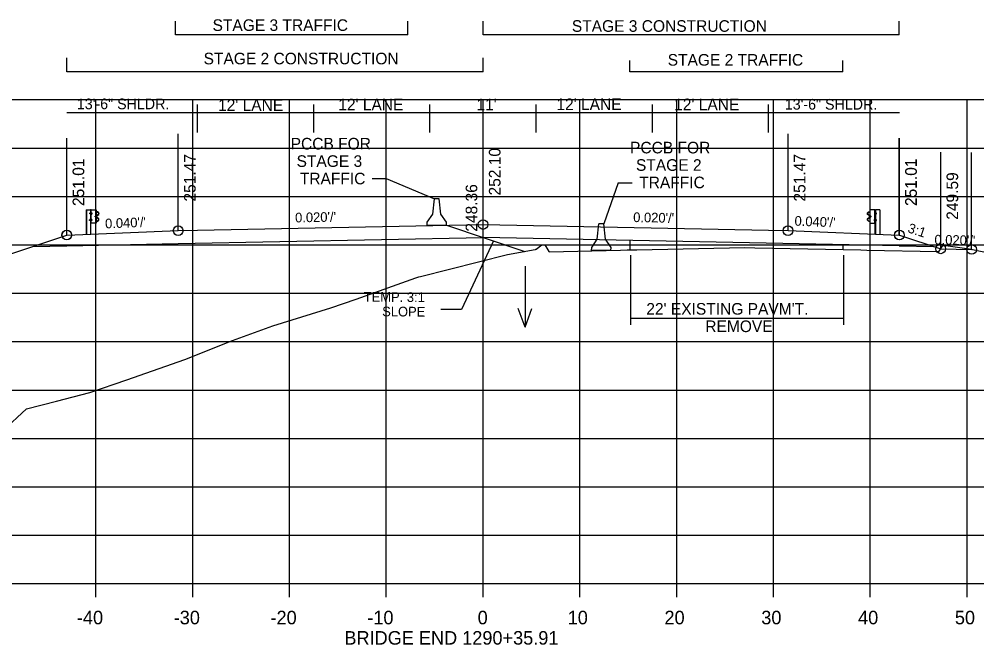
# Model space of a CAD drawing. Extents: x 1342547 to 1344156, y -1532351 to -1517216.
# Drawn here: x 1342654.9 to 1342753.9, y -1521243.9 to -1521179.3 of the extents above; entities that cross this region are included whole.
import ezdxf

# ---------------------------------------------------------------- set-up
doc = ezdxf.new("R2010")
doc.units = 0
for name, color, linetype in [('R_Alt Surface', 7, 'Continuous'), ('R_Axis', 7, 'Continuous'), ('R_Axis Annot', 7, 'Continuous'), ('R_Draft', 7, 'Continuous'), ('R_Exist Surface', 7, 'Continuous'), ('R_Fin Surface', 7, 'Continuous'), ('R_Grid', 7, 'Continuous'), ('R_MOT', 7, 'Continuous'), ('R_No Plot', 7, 'Continuous'), ('R_Water', 7, 'Continuous'), ('R_Xsect Elev', 7, 'Continuous'), ('R_Xsect Slope', 7, 'Continuous')]:
    doc.layers.add(name, color=color, linetype=linetype)

msp = doc.modelspace()

# ---------------------------------------------------------------- linework, layer by layer
at = {"layer": 'R_Alt Surface'}
for points in [[(1342659.865, -1521202.667), (1342671.365, -1521202.437), (1342702.865, -1521201.807)], [(1342745.865, -1521202.667), (1342702.865, -1521201.807)], [(1342656.338, -1521202.737), (1342659.865, -1521202.667)], [(1342745.865, -1521202.667), (1342749.391, -1521202.737)]]:
    msp.add_lwpolyline(points, dxfattribs=at)
at = {"layer": 'R_Axis'}
for p, q in [((1342562.865, -1521237.573), (1342842.865, -1521237.573)), ((1342662.865, -1521238.973), (1342662.865, -1521237.573)), ((1342672.865, -1521238.973), (1342672.865, -1521237.573)), ((1342682.865, -1521238.973), (1342682.865, -1521237.573)), ((1342692.865, -1521238.973), (1342692.865, -1521237.573)), ((1342702.865, -1521238.973), (1342702.865, -1521237.573)), ((1342712.865, -1521238.973), (1342712.865, -1521237.573)), ((1342722.865, -1521238.973), (1342722.865, -1521237.573)), ((1342732.865, -1521238.973), (1342732.865, -1521237.573)), ((1342742.865, -1521238.973), (1342742.865, -1521237.573)), ((1342752.865, -1521238.973), (1342752.865, -1521237.573))]:
    msp.add_line(p, q, dxfattribs=at)
at = {"layer": 'R_Draft'}
for p, q in [((1342671.098, -1521180.895), (1342671.098, -1521179.464)), ((1342695.098, -1521180.895), (1342695.098, -1521179.464)), ((1342702.865, -1521180.895), (1342702.865, -1521179.464)), ((1342745.865, -1521180.895), (1342745.865, -1521179.464)), ((1342695.098, -1521180.895), (1342671.098, -1521180.895)), ((1342745.865, -1521180.895), (1342702.865, -1521180.895)), ((1342659.855, -1521184.691), (1342659.855, -1521183.26)), ((1342702.865, -1521184.691), (1342702.865, -1521183.26)), ((1342718.03, -1521184.691), (1342718.03, -1521183.546)), ((1342740.032, -1521184.691), (1342740.032, -1521183.546)), ((1342702.865, -1521184.691), (1342659.855, -1521184.691)), ((1342740.032, -1521184.691), (1342718.03, -1521184.691)), ((1342661.857, -1521198.961), (1342661.857, -1521201.476)), ((1342661.887, -1521198.961), (1342661.887, -1521201.476)), ((1342662.257, -1521199.371), (1342662.257, -1521199.277)), ((1342662.312, -1521199.387), (1342662.262, -1521199.387)), ((1342662.312, -1521199.292), (1342662.263, -1521199.292)), ((1342662.312, -1521199.356), (1342662.263, -1521199.356)), ((1342662.312, -1521199.262), (1342662.264, -1521199.262)), ((1342662.312, -1521199.356), (1342662.269, -1521199.356)), ((1342662.312, -1521199.387), (1342662.312, -1521199.262)), ((1342662.382, -1521198.959), (1342662.313, -1521198.962)), ((1342662.348, -1521201.477), (1342662.348, -1521198.959)), ((1342662.382, -1521198.959), (1342662.376, -1521198.959)), ((1342662.437, -1521199.33), (1342662.381, -1521199.33)), ((1342662.388, -1521199.392), (1342662.438, -1521199.392)), ((1342662.389, -1521199.267), (1342662.438, -1521199.267)), ((1342662.438, -1521199.267), (1342662.438, -1521199.392)), ((1342662.881, -1521200.327), (1342662.881, -1521198.967)), ((1342663.025, -1521199.175), (1342662.913, -1521199.115)), ((1342663.012, -1521199.191), (1342662.919, -1521199.141)), ((1342662.967, -1521199.507), (1342663.139, -1521199.402)), ((1342662.98, -1521199.528), (1342663.152, -1521199.423)), ((1342663.142, -1521199.295), (1342663.012, -1521199.191)), ((1342663.155, -1521199.279), (1342663.025, -1521199.175)), ((1342742.567, -1521199.281), (1342742.697, -1521199.177)), ((1342742.742, -1521199.53), (1342742.57, -1521199.425)), ((1342742.58, -1521199.297), (1342742.71, -1521199.193)), ((1342742.755, -1521199.509), (1342742.583, -1521199.404)), ((1342742.697, -1521199.177), (1342742.809, -1521199.117)), ((1342742.71, -1521199.193), (1342742.803, -1521199.143)), ((1342742.841, -1521200.329), (1342742.841, -1521198.969)), ((1342743.333, -1521199.269), (1342743.284, -1521199.269)), ((1342743.284, -1521199.269), (1342743.284, -1521199.394)), ((1342743.334, -1521199.394), (1342743.284, -1521199.394)), ((1342743.285, -1521199.332), (1342743.341, -1521199.332)), ((1342743.34, -1521198.961), (1342743.346, -1521198.961)), ((1342743.34, -1521198.961), (1342743.409, -1521198.964)), ((1342743.374, -1521201.479), (1342743.374, -1521198.961)), ((1342743.41, -1521199.389), (1342743.41, -1521199.264)), ((1342743.41, -1521199.264), (1342743.458, -1521199.264)), ((1342743.41, -1521199.294), (1342743.459, -1521199.294)), ((1342743.41, -1521199.358), (1342743.453, -1521199.358)), ((1342743.41, -1521199.358), (1342743.459, -1521199.358)), ((1342743.41, -1521199.389), (1342743.46, -1521199.389)), ((1342743.465, -1521199.373), (1342743.465, -1521199.279)), ((1342743.835, -1521198.963), (1342743.835, -1521201.478)), ((1342743.865, -1521198.963), (1342743.865, -1521201.478)), ((1342662.247, -1521200.061), (1342662.247, -1521199.966)), ((1342662.302, -1521199.982), (1342662.252, -1521199.982)), ((1342662.302, -1521200.046), (1342662.252, -1521200.046)), ((1342662.302, -1521200.076), (1342662.252, -1521200.076)), ((1342662.302, -1521199.951), (1342662.253, -1521199.951)), ((1342662.302, -1521200.046), (1342662.259, -1521200.046)), ((1342662.302, -1521200.076), (1342662.302, -1521199.951)), ((1342662.381, -1521200.327), (1342662.347, -1521200.327)), ((1342662.437, -1521200.014), (1342662.381, -1521200.014)), ((1342662.438, -1521200.076), (1342662.388, -1521200.076)), ((1342662.438, -1521199.951), (1342662.389, -1521199.951)), ((1342662.438, -1521200.076), (1342662.438, -1521199.951)), ((1342662.813, -1521199.693), (1342662.813, -1521199.598)), ((1342662.868, -1521199.708), (1342662.818, -1521199.708)), ((1342662.868, -1521199.614), (1342662.819, -1521199.614)), ((1342662.868, -1521199.678), (1342662.819, -1521199.678)), ((1342662.868, -1521199.583), (1342662.82, -1521199.583)), ((1342662.868, -1521199.678), (1342662.825, -1521199.678)), ((1342662.868, -1521199.708), (1342662.868, -1521199.583)), ((1342662.909, -1521200.165), (1342663.017, -1521200.11)), ((1342662.917, -1521200.184), (1342663.031, -1521200.126)), ((1342662.92, -1521199.707), (1342662.922, -1521199.576)), ((1342662.944, -1521199.708), (1342662.946, -1521199.576)), ((1342663.117, -1521199.879), (1342662.962, -1521199.782)), ((1342663.129, -1521199.859), (1342662.975, -1521199.762)), ((1342663.017, -1521200.11), (1342663.143, -1521200.001)), ((1342663.031, -1521200.126), (1342663.157, -1521200.017)), ((1342742.691, -1521200.128), (1342742.565, -1521200.019)), ((1342742.705, -1521200.112), (1342742.579, -1521200.003)), ((1342742.593, -1521199.861), (1342742.747, -1521199.764)), ((1342742.605, -1521199.881), (1342742.76, -1521199.784)), ((1342742.805, -1521200.186), (1342742.691, -1521200.128)), ((1342742.813, -1521200.167), (1342742.705, -1521200.112)), ((1342742.778, -1521199.71), (1342742.776, -1521199.578)), ((1342742.802, -1521199.709), (1342742.8, -1521199.578)), ((1342742.854, -1521199.71), (1342742.854, -1521199.585)), ((1342742.854, -1521199.585), (1342742.902, -1521199.585)), ((1342742.854, -1521199.616), (1342742.903, -1521199.616)), ((1342742.854, -1521199.68), (1342742.897, -1521199.68)), ((1342742.854, -1521199.68), (1342742.903, -1521199.68)), ((1342742.854, -1521199.71), (1342742.904, -1521199.71)), ((1342742.909, -1521199.695), (1342742.909, -1521199.6)), ((1342743.284, -1521200.078), (1342743.284, -1521199.953)), ((1342743.284, -1521199.953), (1342743.333, -1521199.953)), ((1342743.284, -1521200.078), (1342743.334, -1521200.078)), ((1342743.285, -1521200.016), (1342743.341, -1521200.016)), ((1342743.341, -1521200.329), (1342743.375, -1521200.329)), ((1342743.42, -1521200.078), (1342743.42, -1521199.953)), ((1342743.42, -1521199.953), (1342743.469, -1521199.953)), ((1342743.42, -1521199.984), (1342743.47, -1521199.984)), ((1342743.42, -1521200.048), (1342743.463, -1521200.048)), ((1342743.42, -1521200.048), (1342743.47, -1521200.048)), ((1342743.42, -1521200.078), (1342743.47, -1521200.078)), ((1342743.475, -1521200.063), (1342743.475, -1521199.968)), ((1342699.091, -1521200.549), (1342707.186, -1521203.247)), ((1342718.029, -1521202.11), (1342718.029, -1521203.094)), ((1342740.03, -1521202.55), (1342740.03, -1521203.059)), ((1342718.085, -1521203.626), (1342718.085, -1521210.823)), ((1342740.087, -1521203.626), (1342740.087, -1521210.823)), ((1342718.085, -1521210.15), (1342740.087, -1521210.15))]:
    msp.add_line(p, q, dxfattribs=at)
for points in [[(1342691.397, -1521195.735), (1342692.838, -1521195.735)], [(1342692.838, -1521195.735), (1342697.84, -1521197.818)], [(1342716.811, -1521196.157), (1342715.327, -1521200.415)], [(1342716.811, -1521196.157), (1342718.253, -1521196.157)], [(1342661.857, -1521198.961), (1342662.313, -1521198.962), (1342662.312, -1521201.477)], [(1342743.865, -1521198.963), (1342743.409, -1521198.964), (1342743.411, -1521201.479)]]:
    msp.add_lwpolyline(points, dxfattribs=at)
for points in [[(1342662.255, -1521199.293), (1342662.255, -1521199.355), (1342662.23, -1521199.355), (1342662.23, -1521199.293)], [(1342662.311, -1521199.242), (1342662.311, -1521199.41), (1342662.321, -1521199.41), (1342662.321, -1521199.242)], [(1342662.907, -1521198.96), (1342662.906, -1521200.327), (1342662.381, -1521200.327), (1342662.382, -1521198.959)], [(1342662.437, -1521199.267), (1342662.437, -1521199.392), (1342662.382, -1521199.392), (1342662.382, -1521199.267)], [(1342742.815, -1521198.962), (1342742.816, -1521200.329), (1342743.341, -1521200.329), (1342743.34, -1521198.961)], [(1342743.285, -1521199.269), (1342743.285, -1521199.394), (1342743.34, -1521199.394), (1342743.34, -1521199.269)], [(1342743.411, -1521199.244), (1342743.411, -1521199.412), (1342743.401, -1521199.412), (1342743.401, -1521199.244)], [(1342743.467, -1521199.295), (1342743.467, -1521199.357), (1342743.492, -1521199.357), (1342743.492, -1521199.295)], [(1342662.244, -1521199.982), (1342662.244, -1521200.045), (1342662.219, -1521200.045), (1342662.219, -1521199.982)], [(1342662.3, -1521199.931), (1342662.3, -1521200.099), (1342662.31, -1521200.099), (1342662.31, -1521199.931)], [(1342662.437, -1521199.951), (1342662.437, -1521200.076), (1342662.382, -1521200.076), (1342662.382, -1521199.951)], [(1342662.811, -1521199.614), (1342662.811, -1521199.677), (1342662.786, -1521199.677), (1342662.786, -1521199.614)], [(1342662.867, -1521199.563), (1342662.867, -1521199.731), (1342662.877, -1521199.731), (1342662.877, -1521199.563)], [(1342742.855, -1521199.565), (1342742.855, -1521199.733), (1342742.845, -1521199.733), (1342742.845, -1521199.565)], [(1342742.911, -1521199.616), (1342742.911, -1521199.679), (1342742.936, -1521199.679), (1342742.936, -1521199.616)], [(1342743.285, -1521199.953), (1342743.285, -1521200.078), (1342743.34, -1521200.078), (1342743.34, -1521199.953)], [(1342743.422, -1521199.933), (1342743.422, -1521200.101), (1342743.412, -1521200.101), (1342743.412, -1521199.933)], [(1342743.478, -1521199.984), (1342743.478, -1521200.047), (1342743.503, -1521200.047), (1342743.503, -1521199.984)]]:
    msp.add_lwpolyline(points, close=True, dxfattribs=at)
for centre, radius, start, end in [((1342662.28, -1521199.278), 0.022, 134.57445, 222.22441), ((1342662.35, -1521199.325), 0.0922, 159.74227, 200.25773), ((1342662.283, -1521199.372), 0.025, 140.93341, 216.62337), ((1342663.008, -1521199.583), 0.0865, 118.10599, 175.04439), ((1342663.109, -1521199.348), 0.062, 299.24991, 57.97825), ((1342663.109, -1521199.348), 0.0856, 299.24991, 57.97825), ((1342742.613, -1521199.35), 0.0856, 122.02175, 240.75009), ((1342742.613, -1521199.35), 0.062, 122.02175, 240.75009), ((1342742.714, -1521199.586), 0.0865, 4.95561, 61.89401), ((1342743.443, -1521199.28), 0.022, 317.77559, 45.42555), ((1342743.373, -1521199.327), 0.0922, 339.74227, 20.25773), ((1342743.44, -1521199.374), 0.025, 323.37663, 39.06659), ((1342662.269, -1521199.967), 0.022, 134.57445, 222.22441), ((1342662.339, -1521200.014), 0.0922, 159.74227, 200.25773), ((1342662.272, -1521200.061), 0.025, 140.93341, 216.62337), ((1342662.836, -1521199.599), 0.022, 134.57445, 222.22441), ((1342662.906, -1521199.646), 0.0922, 159.74227, 200.25773), ((1342662.839, -1521199.693), 0.025, 140.93341, 216.62337), ((1342662.99, -1521199.717), 0.0703, 171.78044, 246.85364), ((1342662.939, -1521199.65), 0.0453, 282.95537, 86.06973), ((1342662.99, -1521199.717), 0.0462, 171.78044, 246.85364), ((1342663.008, -1521199.583), 0.0622, 118.10599, 175.04439), ((1342663.073, -1521199.952), 0.0854, 325.21842, 59.11995), ((1342663.073, -1521199.952), 0.109, 325.21843, 59.11995), ((1342742.649, -1521199.954), 0.109, 120.88005, 214.78158), ((1342742.649, -1521199.954), 0.0854, 120.88005, 214.78158), ((1342742.783, -1521199.652), 0.0453, 93.93027, 257.04463), ((1342742.714, -1521199.586), 0.0622, 4.95561, 61.89401), ((1342742.732, -1521199.72), 0.0462, 293.14636, 8.21956), ((1342742.732, -1521199.72), 0.0703, 293.14636, 8.21956), ((1342742.887, -1521199.601), 0.022, 317.77559, 45.42555), ((1342742.816, -1521199.648), 0.0922, 339.74227, 20.25773), ((1342742.884, -1521199.696), 0.025, 323.37663, 39.06659), ((1342743.453, -1521199.969), 0.022, 317.77559, 45.42555), ((1342743.383, -1521200.016), 0.0922, 339.74227, 20.25773), ((1342743.45, -1521200.064), 0.025, 323.37663, 39.06659)]:
    msp.add_arc(centre, radius, start, end, dxfattribs=at)
at = {"layer": 'R_Exist Surface'}
msp.add_lwpolyline([(1342653.241, -1521221.788), (1342655.707, -1521219.521), (1342658.812, -1521218.723), (1342662.225, -1521217.827), (1342666.057, -1521216.519), (1342672.056, -1521214.425), (1342676.962, -1521212.459), (1342681.13, -1521210.936), (1342687.121, -1521209.066), (1342689.749, -1521208.198), (1342695.909, -1521205.996), (1342696.23, -1521205.883), (1342696.414, -1521205.831), (1342705.387, -1521203.583), (1342708.254, -1521203.048), (1342708.272, -1521203.04), (1342708.322, -1521203.031), (1342708.331, -1521203.022), (1342708.941, -1521202.588), (1342709.103, -1521202.588), (1342709.241, -1521202.588), (1342709.653, -1521203.248), (1342709.68, -1521203.285), (1342717.047, -1521203.122), (1342717.747, -1521203.104), (1342718.747, -1521203.082), (1342729.921, -1521202.855), (1342730.933, -1521202.877), (1342741.887, -1521203.1), (1342742.507, -1521203.111), (1342749.857, -1521203.262), (1342749.942, -1521203.263), (1342749.986, -1521203.225), (1342750.36, -1521202.645), (1342750.487, -1521202.645), (1342750.66, -1521202.645), (1342753.093, -1521203.003), (1342754.766, -1521203.338)], dxfattribs=at)
at = {"layer": 'R_Fin Surface'}
msp.add_lwpolyline([(1342555.604, -1521213.2), (1342586.278, -1521223.424), (1342594.278, -1521223.424), (1342659.855, -1521201.565), (1342659.865, -1521201.563), (1342671.365, -1521201.103), (1342673.365, -1521201.063), (1342702.865, -1521200.473), (1342732.365, -1521201.063), (1342734.365, -1521201.103), (1342745.865, -1521201.564), (1342745.875, -1521201.565), (1342750.14, -1521202.987), (1342753.332, -1521203.051)], dxfattribs=at)
at = {"layer": 'R_Grid'}
for p, q in [((1342562.865, -1521187.573), (1342842.865, -1521187.573)), ((1342662.865, -1521237.573), (1342662.865, -1521187.573)), ((1342672.865, -1521237.573), (1342672.865, -1521187.573)), ((1342682.865, -1521237.573), (1342682.865, -1521187.573)), ((1342692.865, -1521237.573), (1342692.865, -1521187.573)), ((1342702.865, -1521237.573), (1342702.865, -1521187.573)), ((1342712.865, -1521237.573), (1342712.865, -1521187.573)), ((1342722.865, -1521237.573), (1342722.865, -1521187.573)), ((1342732.865, -1521237.573), (1342732.865, -1521187.573)), ((1342742.865, -1521237.573), (1342742.865, -1521187.573)), ((1342752.865, -1521237.573), (1342752.865, -1521187.573)), ((1342562.865, -1521192.573), (1342842.865, -1521192.573)), ((1342562.865, -1521197.573), (1342842.865, -1521197.573)), ((1342562.865, -1521202.573), (1342842.865, -1521202.573)), ((1342562.865, -1521207.573), (1342842.865, -1521207.573)), ((1342562.865, -1521212.573), (1342842.865, -1521212.573)), ((1342562.865, -1521217.573), (1342842.865, -1521217.573)), ((1342562.865, -1521222.573), (1342842.865, -1521222.573)), ((1342562.865, -1521227.573), (1342842.865, -1521227.573)), ((1342562.865, -1521232.573), (1342842.865, -1521232.573)), ((1342562.865, -1521237.573), (1342842.865, -1521237.573))]:
    msp.add_line(p, q, dxfattribs=at)
at = {"layer": 'R_MOT'}
for p, q in [((1342697.673, -1521199.401), (1342697.84, -1521197.818)), ((1342698.09, -1521197.818), (1342697.84, -1521197.818)), ((1342698.34, -1521197.818), (1342698.09, -1521197.818)), ((1342698.508, -1521199.402), (1342698.34, -1521197.818)), ((1342697.098, -1521200.235), (1342697.673, -1521199.401)), ((1342699.098, -1521200.235), (1342698.508, -1521199.402)), ((1342697.091, -1521200.568), (1342697.098, -1521200.235)), ((1342699.091, -1521200.568), (1342699.098, -1521200.235)), ((1342714.66, -1521201.998), (1342714.826, -1521200.415)), ((1342715.076, -1521200.415), (1342714.826, -1521200.415)), ((1342715.327, -1521200.415), (1342715.076, -1521200.415)), ((1342715.494, -1521201.999), (1342715.327, -1521200.415)), ((1342699.091, -1521200.568), (1342697.091, -1521200.568)), ((1342714.084, -1521202.831), (1342714.66, -1521201.998)), ((1342716.084, -1521202.831), (1342715.494, -1521201.999)), ((1342714.077, -1521203.164), (1342714.084, -1521202.831)), ((1342716.078, -1521203.164), (1342714.077, -1521203.164)), ((1342716.078, -1521203.164), (1342716.084, -1521202.831))]:
    msp.add_line(p, q, dxfattribs=at)
at = {"layer": 'R_No Plot'}
for centre in [(1342702.865, -1521200.473), (1342659.855, -1521201.565), (1342659.865, -1521201.563), (1342671.365, -1521201.103), (1342734.365, -1521201.103), (1342745.865, -1521201.564), (1342745.875, -1521201.565), (1342750.14, -1521202.987), (1342753.332, -1521203.051)]:
    msp.add_circle(centre, 0.5, dxfattribs=at)
at = {"layer": 'R_Water'}
for p, q in [((1342707.202, -1521204.78), (1342707.202, -1521211.065)), ((1342707.202, -1521211.065), (1342706.502, -1521209.141)), ((1342707.202, -1521211.065), (1342707.902, -1521209.141))]:
    msp.add_line(p, q, dxfattribs=at)
at = {"layer": 'R_Xsect Elev'}
for p, q in [((1342673.365, -1521190.954), (1342673.365, -1521188.092)), ((1342685.365, -1521190.954), (1342685.365, -1521188.092)), ((1342697.365, -1521190.954), (1342697.365, -1521188.092)), ((1342708.365, -1521190.954), (1342708.365, -1521188.092)), ((1342720.365, -1521190.954), (1342720.365, -1521188.092)), ((1342732.365, -1521190.954), (1342732.365, -1521188.092)), ((1342745.875, -1521188.95), (1342659.865, -1521188.95)), ((1342702.865, -1521200.473), (1342702.865, -1521190.473)), ((1342659.855, -1521201.565), (1342659.855, -1521191.565)), ((1342659.865, -1521201.563), (1342659.865, -1521191.563)), ((1342671.365, -1521201.103), (1342671.365, -1521191.103)), ((1342734.365, -1521201.103), (1342734.365, -1521191.103)), ((1342745.865, -1521201.564), (1342745.865, -1521191.564)), ((1342745.875, -1521201.565), (1342745.875, -1521191.565)), ((1342750.14, -1521202.987), (1342750.14, -1521192.987)), ((1342753.332, -1521203.051), (1342753.332, -1521193.051)), ((1342702.865, -1521204.215), (1342702.865, -1521194.215)), ((1342703.943, -1521202.166), (1342700.64, -1521209.244)), ((1342700.64, -1521209.244), (1342698.498, -1521209.244))]:
    msp.add_line(p, q, dxfattribs=at)

# ---------------------------------------------------------------- texts
at = {"layer": 'R_Axis Annot'}
for s, p in [('-40', (1342660.904, -1521241.773)), ('-30', (1342670.904, -1521241.773)), ('-20', (1342680.904, -1521241.773)), ('-10', (1342690.904, -1521241.773)), ('0', (1342702.304, -1521241.773)), ('10', (1342711.604, -1521241.773)), ('20', (1342721.604, -1521241.773)), ('30', (1342731.604, -1521241.773)), ('40', (1342741.604, -1521241.773)), ('50', (1342751.604, -1521241.773)), ('BRIDGE END 1290+35.91', (1342688.537, -1521243.873))]:
    msp.add_text(s, height=1.4, dxfattribs=at).set_placement(p)
at = {"layer": 'R_Draft'}
for s, p in [('STAGE 3 TRAFFIC', (1342674.917, -1521180.478)), ('STAGE 3 CONSTRUCTION', (1342712.033, -1521180.569)), ('STAGE 2 CONSTRUCTION', (1342673.992, -1521183.928)), ('STAGE 2 TRAFFIC', (1342721.936, -1521184.064)), ('PCCB FOR', (1342682.987, -1521192.724)), ('PCCB FOR', (1342718.049, -1521193.128)), ('STAGE 3', (1342683.597, -1521194.524)), ('STAGE 2', (1342718.658, -1521194.928)), ('TRAFFIC', (1342683.932, -1521196.324)), ('TRAFFIC', (1342718.994, -1521196.728)), ("22' EXISTING PAVM'T.", (1342719.726, -1521209.786)), ('REMOVE', (1342725.821, -1521211.586))]:
    msp.add_text(s, height=1.2, dxfattribs=at).set_placement(p)
at = {"layer": 'R_Xsect Elev'}
for s, height, p in [('13\'-6" SHLDR.', 1.1, (1342660.902, -1521188.563)), ("12' LANE", 1.2, (1342675.484, -1521188.737)), ("12' LANE", 1.2, (1342687.906, -1521188.683)), ("11'", 1.2, (1342702.179, -1521188.683)), ("12' LANE", 1.2, (1342710.443, -1521188.655)), ("12' LANE", 1.2, (1342722.606, -1521188.667)), ('13\'-6" SHLDR.', 1.1, (1342734.035, -1521188.605))]:
    msp.add_text(s, height=height, dxfattribs=at).set_placement(p)
for s, p in [('251.47', (1342673.165, -1521198.103)), ('252.10', (1342704.665, -1521197.473)), ('251.47', (1342736.165, -1521198.103)), ('251.01', (1342661.655, -1521198.565)), ('251.01', (1342661.665, -1521198.563)), ('251.01', (1342747.665, -1521198.564)), ('251.01', (1342747.675, -1521198.565)), ('249.59', (1342751.94, -1521199.987)), ('248.36', (1342702.265, -1521201.215))]:
    msp.add_text(s, height=1.2, rotation=90, dxfattribs=at).set_placement(p)
at = {"layer": 'R_Xsect Slope'}
for s, rotation, p in [("0.020'/'", 1.14576, (1342683.454, -1521200.262)), ("0.020'/'", 358.85424, (1342718.363, -1521200.216)), ("0.040'/'", 2.29061, (1342663.835, -1521200.88)), ("0.040'/'", 357.70774, (1342735.024, -1521200.588)), ('3:1', 341.56507, (1342746.653, -1521201.256)), ("0.020'/'", 358.85424, (1342749.486, -1521202.532)), ('TEMP. 3:1', 359.62418, (1342690.527, -1521208.443)), ('SLOPE', 359.62418, (1342692.437, -1521209.955))]:
    msp.add_text(s, height=1, rotation=rotation, dxfattribs=at).set_placement(p)

doc.saveas('drawing.dxf')
